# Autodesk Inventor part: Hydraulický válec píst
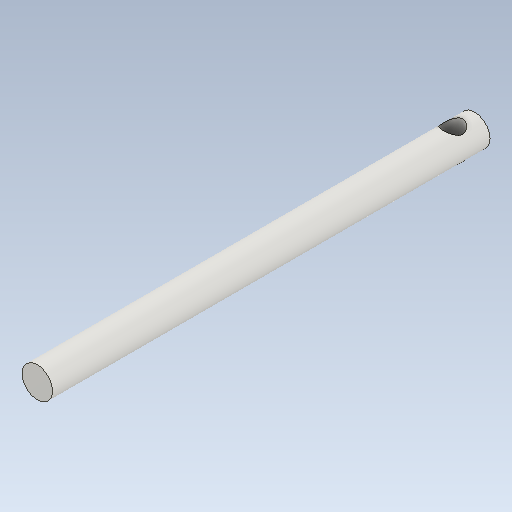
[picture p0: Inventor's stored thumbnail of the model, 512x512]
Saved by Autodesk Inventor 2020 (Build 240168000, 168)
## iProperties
Created: 2025-03
Part Number: Hydraulický válec píst
Material: Ocel
Document SubType Name: Modeling
Designer: doma
Density: 7.85 g/cm^3
Appearance: Ocel
Mass: 235.066 g
Surface Area: 93.1967 cm^2
Volume: 29.9447 cm^3
Author: doma
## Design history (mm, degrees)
sketch "Náčrt1"
  geometry: C1 r 7 at (0, 0); 1 further point
  constraints: 1 centre point, 1 coincident
  dimensions: "d0" = 14 diameter of C1
extrude "Vysunutí1" new body sketch "Náčrt1" distance "d1" = 200; taper "d2" = 0 deg
sketch "Náčrt2"
  geometry: L1 (7, 0)-(-7, 0) reference; C1 r 4.5 at (0, 10); 1 further point
  constraints: 1 centre point
  dimensions: "d3" = 9 diameter of C1; "d4" = 10 distance from line of L1 C1.centre
extrude "Vysunutí2" cut sketch "Náčrt2" extent not by distance; stored distance "d5" = 7; taper "d6" = 0 deg
node "Těleso1"
